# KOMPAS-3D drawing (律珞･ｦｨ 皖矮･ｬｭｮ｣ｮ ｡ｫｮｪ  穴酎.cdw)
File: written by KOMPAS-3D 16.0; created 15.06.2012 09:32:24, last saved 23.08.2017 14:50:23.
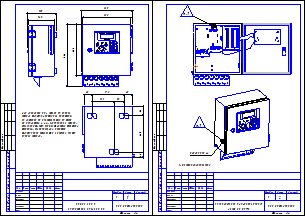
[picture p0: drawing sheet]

Sheets 1-2: A4, portrait

Title block, sheet 1: sheet number: 1; sheets: 29; organisation: ООО"Интелприбор"; sheet format: A4; stored path: D:\Проекты\Лыткарино\ул. Октябрьская, д.18\710.103 РП.cdw; cell 51: МО, Воскресенсикй р-н, п. Хорлово, ул. Интернациональная, д. 4; cell 320: Р
Title block, sheet 2: sheet number: 2; sheet number: 30; stored path: D:\Общее для проектов\Шаблон проекта\5-ти трубная система\5-х трубная шаблон.cdw

Views: Вид 2, Вид 3
Referenced files in C:\Program Files (x86)\ASCON\KOMPAS-3D V16\Sys\: spds.lcs, EngSys.lcs, GRAPHIC.LHS
Referenced files: graphic.tdp
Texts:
  Смирнов В.С.
  УУ-3423
  GOST Common
  Normal
  List Paragraph
  heading 3
  для схемы
  txt
  Размеры, параметризация
  сит. план
  подача ГВС
  обратка ГВС
  хвс
  обратка
  POLYLINE_STYLE_0.25_RGB_0_0_0
  стены
  Основная (не является границей для штриховки)
  POLYLINE_STYLE_0.18_RGB_0_0_0
  ХВС
  зеленая
  Красная тонкая
  арматура
  Подача
  Скрытая линия
  Ось Z
  Ось Y
  Ось X
  Образующая трубопровода (проектируемого)
  Трубопровод толщиной 0.6мм (одна линия)
  Трубопровод толщиной 1.2мм (одна линия)
  Трубопровод толщиной 1.0мм (одна линия)
  Трубопровод толщиной 0.8мм (одна линия)
  Трубопровод существующий (одна линия)
  Трубопровод невидимый (одна линия)
  Трубопровод демонтируемый (одна линия)
  Осевая трубопровода
  Осевая трубопровода (демонтируемого)
  Образующая трубопровода (существующего)
  Образующая трубопровода (невидимого)
  Изолированный трубопровод проектируемый (одна линия)
  Изолированный трубопровод существующий (одна линия)
  Образующая изоляции
  Изоляция
  Изолированный трубопровод невидимый (одна линия)
  Штрих пвс 075
  штрих пвс 2,5
  существующее оборудование
  Существующее оборудование
  K5LT_BASIC_RGB_0_0_255_THICK_0.53
  POLYLINE_STYLE_1.51_RGB_0_0_255
  POLYLINE_STYLE_0.50_RGB_128_128_128
  K5LT_AXLED_RGB_255_128_0_SC_1_THICK_0.18
  ACAD_ISO04W100_RGB_0_0_0_SC_1_THICK_0.18
  тонкая черная
  тонкая красная
  тонкая синяя
  тонкая оранж
  красн штрих
  пломбировка
  Провода
  синий штрих
  Стили документа
  G2co
  расход вторичной воды объемный
  расход вторичной воды объемный при 70гр
  Gco
  расход теплоносителя массовый
  расход теплоносит объемн подающ
  расход теплоносит объемн обр
  Лапир
  Ghvs
  Im1
  Im2
  Im3
  Im4
  Im5
  Khvs
  норматив ХВС
  число подъездов
  число этажей
  Nkv
  число квартир
  тепловая нагрузка на отопление
  сумма Q
  Qgvs
  тепловая нагрузка ГВС
  тепловая нагрузка на циркуляцию ГВС
  иммитовставка или под манометр
  ro1
  ro2
  ro3
  ro4
  верх предел темп граф
  нижн предел темп граф
  темп подачи ГВС
  темп обр ГВС
  темр хол воды
  vzdh
  Kchn
  Ktp
  Knp
  tnv
  Vклап
  KLP
  RPD
  RDS
  PUMP
  ro5
  beta
  tnv98
  Shifr
  Переход ГОСТ 17378-2001
  Переход
  ГОСТ
  Сталь 09Г2С ГОСТ 19281-89
  Втулка 20x50
  Лит-Масса-Масштаб
  Материал-Предприятие
  Title Specification
  Body Specification ( left align )
  Body Specificaton ( centered )
  Поз.
  Кол.
  Приме-
  чание
  Таблица спецификации
  Засыпка
  Штрих3
  Штрих2
  Штрих1
  Песок
  Штр0.5пр7
  Штр0.5пр12
  Штр0.3пр10
  Штр1.4пр21.21
  Штр1пр15
  Штр2.12пр35
  Штр1.5пр25
  Штр2.82пр42.42
  Штр2пр30
  SACNCR_ISO 1
  Электрощитовая
  Пр-1
  Ок-1
  Обозначение стандарта
  Типоразмер
  Пояснительная записка
  Разраб.
  Пров.
  Т.контр.
  Н.контр.
  Утв.
  Общий вид и
  габаритные размеры СБ
  Рабочие чертежи основного комплекта. ГОСТ Р 21.1101-2009 Ф3
  Стадия
  Лист
  Листов
  Изм.
  Кол.уч.
  №док.
  Подп.
  Дата
  Изменение
  Номер документа
  Подпись
  Наименование объекта строительства, в состав которого входит здание, наим. микр
  Наименование здания (сооружения)
  Порядковый номер листа
  Количество листов в документе
  Наименование изображения
  Индекс предприятия, выпускающего документ
  Инв. № подл.
  Подп. и дата
  Взам. инв. №
  Инвентарный номер подлинника
  Подпись принявшего подлинник на хранение
  Инвентарный номер подлинника, взамен которого выпущен данный подлинник
  Согласовано
  Формат листа
  Согласование
  03 Рабочие чертежи основного комплекта. ГОСТ Р 21.1101-2009 Ф3
  Расположение пломбировочных
  мест СБ МКТС
Dimensions and other numbers on the sheet: 09Г2С; 1; 20; 5; 29; 30; 2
